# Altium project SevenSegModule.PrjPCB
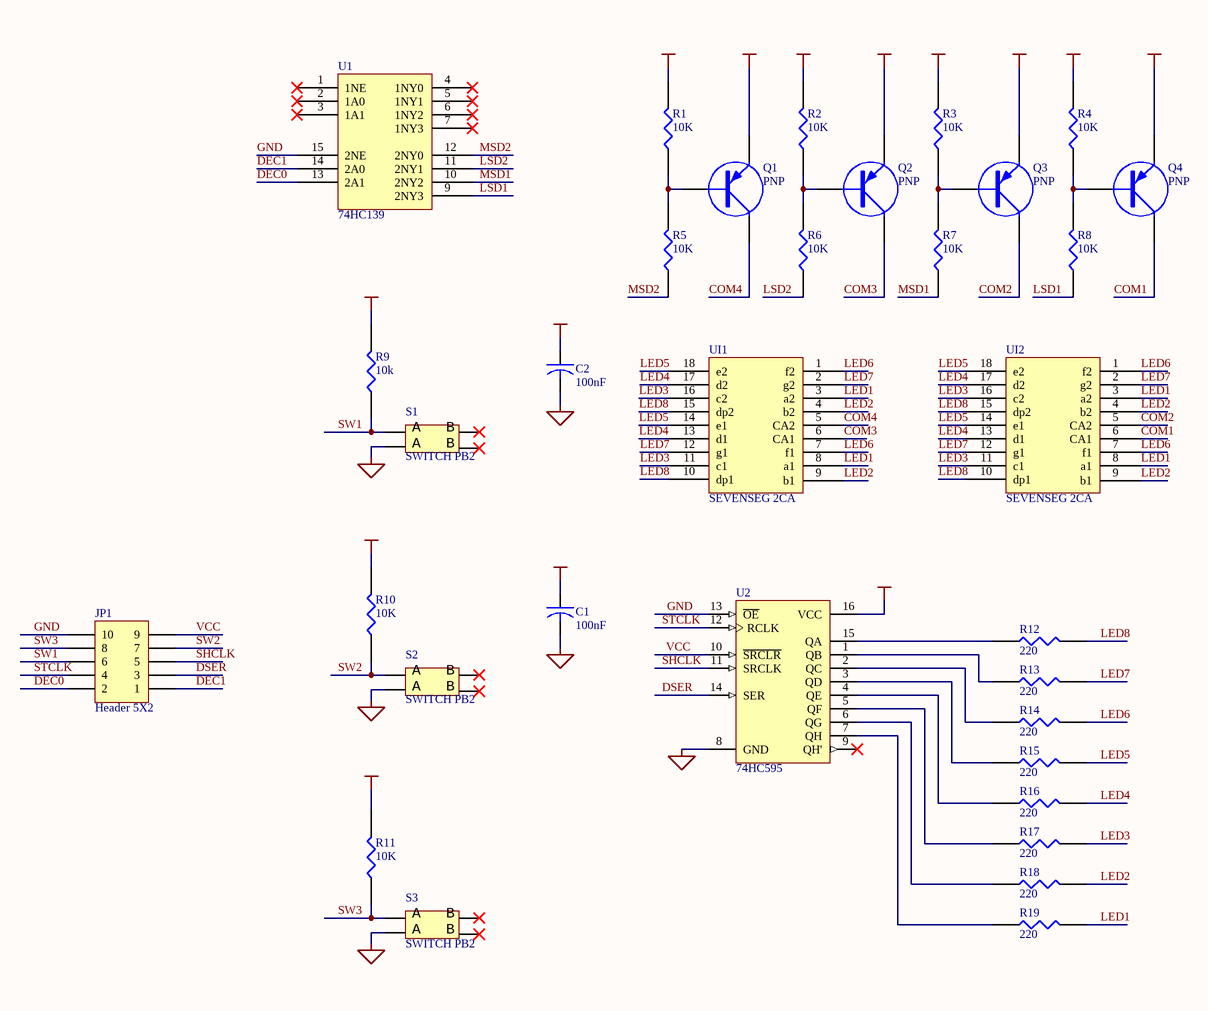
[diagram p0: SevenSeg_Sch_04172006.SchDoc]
1 sheet, 33 parts. Net scope: global (net labels, ports and power ports of the same name join across sheets).
Board files: Seven Seg_Pcb_autoroute.PcbDoc, Seven Seg_Pcb_04182006.PcbDoc

## Sheet SevenSeg_Sch_04172006.SchDoc
size B

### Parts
C1  100nF  [CAP Circ/0.1]
C2  100nF  [CAP Circ/0.1]
JP1  Header 5X2  [HDR2X5]
Q1  PNP  [BC548]
Q2  PNP  [BC548]
Q3  PNP  [BC548]
Q4  PNP  [BC548]
R1  10K  [RES]
R2  10K  [RES]
R3  10K  [RES]
R4  10K  [RES]
R5  10K  [RES]
R6  10K  [RES]
R7  10K  [RES]
R8  10K  [RES]
R9  10k  [RES]
R10  10K  [RES]
R11  10K  [RES]
R12  220  [RES]
R13  220  [RES]
R14  220  [RES]
R15  220  [RES]
R16  220  [RES]
R17  220  [RES]
R18  220  [RES]
R19  220  [RES]
S1  SWITCH PB2  [SWITCH PB2]
S2  SWITCH PB2  [SWITCH PB2]
S3  SWITCH PB2  [SWITCH PB2]
U1  74HC139  [DIP16]
U2  74HC595  [DIP16]
UI1  SEVENSEG 2CA  [SEVENTSEGMENT2]
UI2  SEVENSEG 2CA  [SEVENTSEGMENT2]

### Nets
GND: C1.2 C2.2 JP1.10 S1.2 S2.2 S3.2 U1.8(GND) U1.15(2NE) U2.8(GND) U2.13(~{OE})
VCC: C1.1 C2.1 JP1.9 Q1.1(E) Q2.1(E) Q3.1(E) Q4.1(E) R1.2 R2.2 R3.2 R4.2 R9.2 R10.2 R11.2 U1.16(VCC) U2.10(~{SRCLR}) U2.16(VCC)
COM1: Q4.3(C) UI2.6(CA1)
COM2: Q3.3(C) UI2.5(CA2)
COM3: Q2.3(C) UI1.6(CA1)
COM4: Q1.3(C) UI1.5(CA2)
DEC0: JP1.2 U1.13(2A1)
DEC1: JP1.1 U1.14(2A0)
DSER: JP1.3 U2.14(SER)
LED1: R19.2 UI1.3(a2) UI1.8(a1) UI2.3(a2) UI2.8(a1)
LED2: R18.2 UI1.4(b2) UI1.9(b1) UI2.4(b2) UI2.9(b1)
LED3: R17.2 UI1.11(c1) UI1.16(c2) UI2.11(c1) UI2.16(c2)
LED4: R16.2 UI1.13(d1) UI1.17(d2) UI2.13(d1) UI2.17(d2)
LED5: R15.2 UI1.14(e1) UI1.18(e2) UI2.14(e1) UI2.18(e2)
LED6: R14.2 UI1.1(f2) UI1.7(f1) UI2.1(f2) UI2.7(f1)
LED7: R13.2 UI1.2(g2) UI1.12(g1) UI2.2(g2) UI2.12(g1)
LED8: R12.2 UI1.10(dp1) UI1.15(dp2) UI2.10(dp1) UI2.15(dp2)
LSD1: R8.1 U1.9(2NY3)
LSD2: R6.1 U1.11(2NY1)
MSD1: R7.1 U1.10(2NY2)
MSD2: R5.1 U1.12(2NY0)
SHCLK: JP1.5 U2.11(SRCLK)
STCLK: JP1.4 U2.12(RCLK)
SW1: JP1.6 R9.1 S1.1
SW2: JP1.7 R10.1 S2.1
SW3: JP1.8 R11.1 S3.1
NetQ1_2: Q1.2(B) R1.1 R5.2
NetQ2_2: Q2.2(B) R2.1 R6.2
NetQ3_2: Q3.2(B) R3.1 R7.2
NetQ4_2: Q4.2(B) R4.1 R8.2
NetR12_1: R12.1 U2.15(QA)
NetR13_1: R13.1 U2.1(QB)
NetR14_1: R14.1 U2.2(QC)
NetR15_1: R15.1 U2.3(QD)
NetR16_1: R16.1 U2.4(QE)
NetR17_1: R17.1 U2.5(QF)
NetR18_1: R18.1 U2.6(QG)
NetR19_1: R19.1 U2.7(QH)

Not connected (* = marked no-connect by the designer): S1 3* 4*; S2 3* 4*; S3 3* 4*; U1 1(1NE)* 2(1A0)* 3(1A1)* 4(1NY0)* 5(1NY1)* 6(1NY2)* 7(1NY3)*; U2 9(QH')*

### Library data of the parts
C1 C2 = CAPACITOR
JP1 = Header 5X2: Header, 5-Pin, Dual row; Manufacturer: Generic Components; Class I: Connector
Q1-Q4 = PNP: PNP Transistor
R1-R19 = RES
U1 = 74HC139: 2-to-4 Decoder
U2 = 74HC595: 8 Bit Shift Register with Output Latches (3 STATE); Manufacturer: ST-Microelectronics; Class I: Logic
